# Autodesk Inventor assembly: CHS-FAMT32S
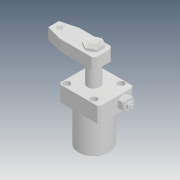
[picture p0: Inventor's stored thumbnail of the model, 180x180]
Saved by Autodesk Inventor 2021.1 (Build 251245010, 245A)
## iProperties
Created: 2020-02
Part Number: CHS-FAMT32S
Description: STEP AP214
Document SubType Name: Assembly
Designer: user
Title: chs-famt32s_asm.STEP
Revision Number: ÈÎºÎ
Sending System: SolidWorks 2016
Preprocessor: SwSTEP 2.0
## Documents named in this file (8)
- D:\Vault_2016\Projekty\Clamptek\Hydraulic\CHS\CHS-32\Inventor\CHS-FAMT32S\CHS-FAMT32S.iam
- D:\Vault_2016\Projekty\Clamptek\Hydraulic\CHS\CHS-32\Inventor\CHS-FAMT32S\CHS-32S-02_3.ipt
- D:\Vault_2016\Projekty\Clamptek\Hydraulic\CHS\CHS-32\Inventor\CHS-FAMT32S\CHS-32S-01_4.ipt
- D:\Vault_2016\Projekty\Clamptek\Hydraulic\CHS\CHS-32\Inventor\CHS-FAMT32S\M16_4.ipt
- D:\Vault_2016\Projekty\Clamptek\Hydraulic\CHS\CHS-32\Inventor\CHS-FAMT32S\CHS-FAMT32BT.ipt
- D:\Vault_2016\Projekty\Clamptek\Hydraulic\CHS\CHS-32\Inventor\CHS-FAMT32S\20·§Ìå.ipt
- D:\Vault_2016\Projekty\Clamptek\Hydraulic\CHS\CHS-32\Inventor\CHS-FAMT32S\20µ÷ËÙ¸Ë.ipt
- D:\Vault_2016\Projekty\Clamptek\Hydraulic\CHS\CHS-32\Inventor\CHS-FAMT32S\hex thin nuts-grades ab-chamfered gb(GB_FASTENER_NUT_STNAB M6-S).ipt
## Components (7 placed, 7 different names)
1. CHS-32S-02_3_1
2. CHS-32S-01_4_2
3. M16_4_3
4. CHS-FAMT32BT_4
5. 20·§Ìå_5
6. 20µ÷ËÙ¸Ë_6
7. hex thin nuts-grades ab-chamfered gb(GB_FASTENER_NUT_STNAB M6-S)_7
